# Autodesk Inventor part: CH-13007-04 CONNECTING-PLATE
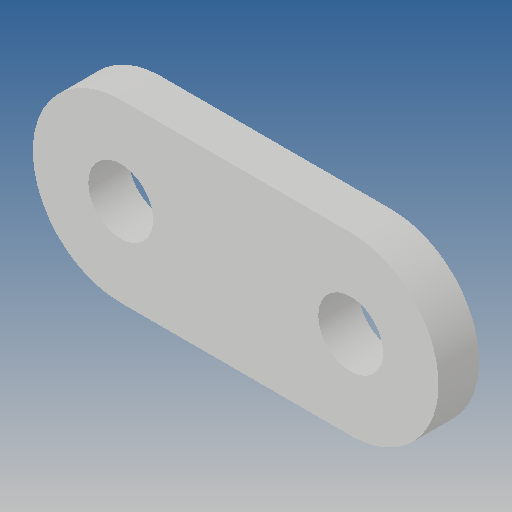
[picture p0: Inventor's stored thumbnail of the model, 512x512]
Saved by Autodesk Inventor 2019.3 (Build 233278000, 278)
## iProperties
Created: 2012-09
Part Number: CH-13007-04 CONNECTING-PLATE
Material: Ogólny
Document SubType Name: Modeling
Designer: CADENGINEERING4
Density: 1 g/cm^3
Appearance: Domyślna
Author: CADENGINEERING4
Revision Number: ÈÎºÎ
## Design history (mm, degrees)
feature "À­Éì1"
node "Bryła1"
